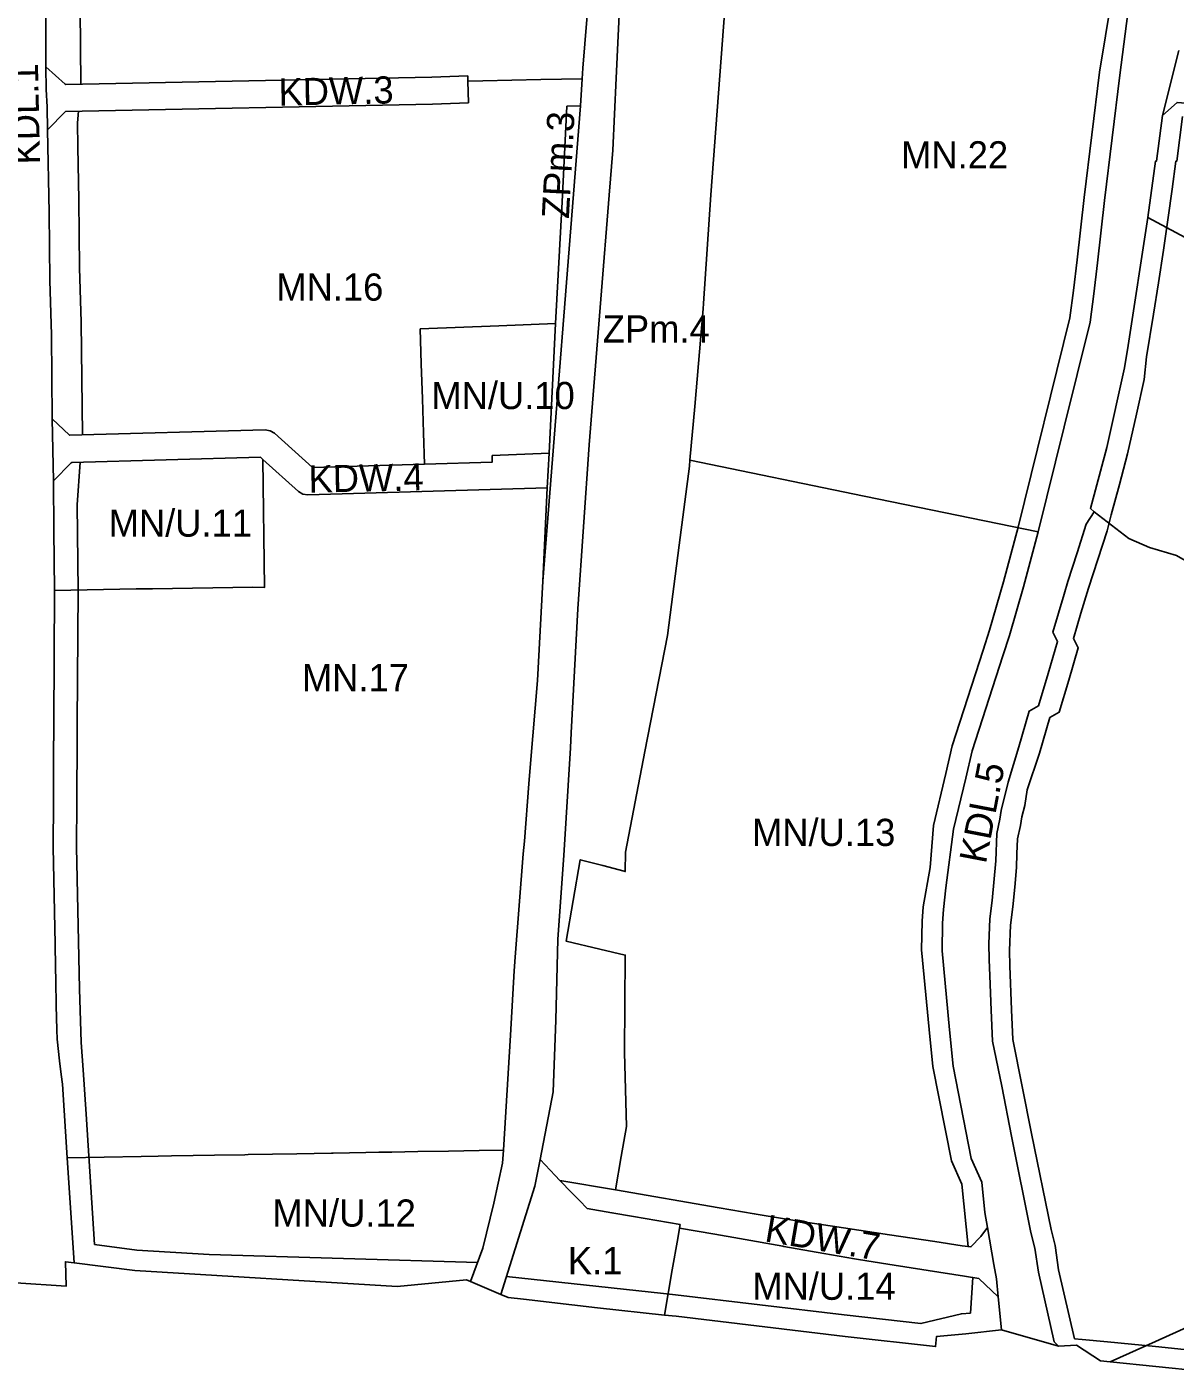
# Model space of a CAD drawing. Extents: x 7431080 to 7433370, y 5546450 to 5548428.
# Drawn here: x 7431653 to 7431991, y 5546819.9 to 5547216.3 of the extents above; entities that cross this region are included whole.
import ezdxf

# ---------------------------------------------------------------- set-up
doc = ezdxf.new("R2010")
doc.units = 0
for name, color, linetype in [('Linie Rozgraniczajace', 7, 'Continuous'), ('nieprzekraczalna linia zabudowy', 7, 'Continuous'), ('oznaczenia_przeznaczen', 7, 'Continuous')]:
    doc.layers.add(name, color=color, linetype=linetype)

msp = doc.modelspace()

# ---------------------------------------------------------------- linework, layer by layer
at = {"layer": 'Linie Rozgraniczajace'}
for p, q in [((7431987.26, 5547190.2), (7431992.07, 5547209.36)), ((7431899.47, 5547078.11), (7431848.17, 5547088.66)), ((7431899.47, 5547078.11), (7431950.67, 5547067.58)), ((7431855.47, 5546860.82), (7431845.13, 5546862.62))]:
    msp.add_line(p, q, dxfattribs=at)
for points in [[(7431658.97, 5547357.52), (7431659.12, 5547345.2), (7431761.61, 5547282.96), (7431765.2, 5547268.96), (7431784.34, 5547269.17), (7431806.85, 5547248.07), (7431819.14, 5547234.05), (7431816.7, 5547204.08)], [(7431982.69, 5547268.13), (7431981.23, 5547251.74), (7431978.31, 5547229.55), (7431974.71, 5547202.02), (7431970.19, 5547165.15), (7431968.19, 5547146.81), (7431967.04, 5547137.69), (7431965.97, 5547129.38), (7431958.32, 5547098.48), (7431950.67, 5547067.58), (7431946.36, 5547051.38), (7431942.22, 5547037.08), (7431940.3, 5547031.13), (7431931.28, 5547003.09), (7431929.38, 5546995.1), (7431925.81, 5546980.02), (7431923.56, 5546962.78), (7431922.79, 5546956.43), (7431922.55, 5546952.38), (7431922.4, 5546944.22), (7431924.59, 5546921)], [(7431658.63, 5547197.82), (7431658.6, 5547204.53), (7431658.49, 5547233.33)], [(7431807.96, 5546902.76), (7431808.69, 5546923.81), (7431809.32, 5546947.71), (7431811.09, 5546972.31), (7431812.99, 5547003.97), (7431813.23, 5547008.39), (7431815.18, 5547044.96), (7431818.54, 5547093.2), (7431821.95, 5547136.09), (7431824.4, 5547166.73), (7431825.46, 5547180), (7431826.45, 5547201.22), (7431827.63, 5547226.19)], [(7431859.01, 5547227.55), (7431858.87, 5547226.83), (7431854.38, 5547166.78), (7431852.22, 5547134.82)], [(7431782.8, 5547201.87), (7431772.18, 5547201.49), (7431664.42, 5547199.34), (7431664.32, 5547199.46), (7431658.6, 5547204.53)], [(7431816.7, 5547204.08), (7431816.5, 5547201), (7431816, 5547193.05)], [(7431782.8, 5547201.87), (7431782.83, 5547200.31), (7431782.97, 5547193.87)], [(7431782.83, 5547200.31), (7431787.25, 5547200.4), (7431795.71, 5547200.57), (7431804.26, 5547200.75), (7431816.5, 5547201)], [(7431659.09, 5547185.94), (7431658.97, 5547192.76), (7431658.63, 5547197.82)], [(7431782.97, 5547193.87), (7431772.43, 5547193.49), (7431772.4, 5547193.5), (7431772.37, 5547193.5), (7431664.34, 5547191.34), (7431659.09, 5547185.94)], [(7431811.96, 5547192.91), (7431810.58, 5547164.75), (7431808.64, 5547128.91), (7431806.7, 5547090.74), (7431806.18, 5547080.57), (7431804.92, 5547053.09), (7431803.27, 5547023.8), (7431801.27, 5546999.43), (7431800.79, 5546993.42), (7431799.46, 5546976.52), (7431799.14, 5546972.84), (7431796.72, 5546942.37), (7431796.47, 5546938.37), (7431795.33, 5546919.43), (7431793.28, 5546885.58), (7431793.05, 5546881.76), (7431790.42, 5546869.94), (7431787.25, 5546856.75), (7431783.62, 5546846.91)], [(7431816, 5547193.05), (7431804.92, 5547053.09)], [(7431811.96, 5547192.91), (7431816, 5547193.05)], [(7431987.26, 5547190.2), (7431985.48, 5547176.73), (7431985.24, 5547176.76), (7431983.01, 5547160.16), (7431977.16, 5547122.42), (7431976.14, 5547115.9), (7431970.95, 5547092.43), (7431966.08, 5547074.52), (7431967.2, 5547073.49), (7431977.34, 5547065.69)], [(7431987.26, 5547190.2), (7431991.61, 5547194.02), (7431996.84, 5547193.65), (7432006.09, 5547192.99), (7432023.49, 5547191.71), (7432040.89, 5547190.43), (7432050.86, 5547189.69), (7432060.83, 5547188.95), (7432081.02, 5547189.02), (7432086.97, 5547188.95), (7432092.93, 5547188.88), (7432094.88, 5547189.01), (7432102.42, 5547188.78), (7432106.42, 5547188.66), (7432117.96, 5547188.31), (7432128.08, 5547187.88), (7432138.21, 5547187.45), (7432142.09, 5547187.22), (7432149.05, 5547187.07), (7432150.13, 5547186.96), (7432151.99, 5547185.41)], [(7431983.01, 5547160.16), (7431996.75, 5547152.83), (7432010.48, 5547145.51), (7432018.88, 5547140.48), (7432027.28, 5547135.45), (7432036.46, 5547129.95), (7432045.63, 5547124.44), (7432053.23, 5547156.7), (7432060.83, 5547188.95)], [(7431659.52, 5547161.65), (7431659.09, 5547185.94)], [(7431660.26, 5547125.65), (7431659.76, 5547141.65), (7431659.52, 5547161.65)], [(7431834.93, 5547002.96), (7431841.55, 5547037.1), (7431845.01, 5547063.71), (7431848.01, 5547086.91), (7431848.17, 5547088.66), (7431849.64, 5547104.47), (7431852.1, 5547133.24), (7431852.22, 5547134.82)], [(7431768.8, 5547127.4), (7431791.91, 5547128.28), (7431808.64, 5547128.91)], [(7431768.8, 5547127.4), (7431769.11, 5547117.08), (7431769.42, 5547106.76), (7431769.73, 5547096.76), (7431770.01, 5547087.51)], [(7431660.96, 5547068.07), (7431660.8, 5547082.63), (7431660.49, 5547100.85), (7431660.26, 5547125.65)], [(7431806.7, 5547090.74), (7431790, 5547090.06), (7431789.95, 5547088.1), (7431770.01, 5547087.51), (7431737.07, 5547086.54), (7431725.89, 5547096.61), (7431724.6, 5547097.39), (7431723.11, 5547097.64), (7431665.54, 5547096.04), (7431660.49, 5547100.85)], [(7431806.18, 5547080.57), (7431735.71, 5547078.5), (7431734.2, 5547078.74), (7431732.91, 5547079.53), (7431722.45, 5547088.95), (7431721.73, 5547089.6), (7431666.27, 5547088.05), (7431666.06, 5547087.91), (7431660.8, 5547082.63)], [(7431661.15, 5547050.37), (7431685.13, 5547050.79), (7431689.99, 5547050.87), (7431719.54, 5547051.34), (7431722.99, 5547051.23), (7431722.45, 5547088.95)], [(7431936.14, 5546946.28), (7431936.42, 5546953.71), (7431937.15, 5546959.11), (7431938.23, 5546970.71), (7431938.51, 5546978.76), (7431939.39, 5546983.03), (7431939.82, 5546985.55), (7431941.85, 5546993.89), (7431944.96, 5547004.35), (7431948.07, 5547014.81), (7431950.8, 5547016.4), (7431953.6, 5547025.86), (7431956.41, 5547035.32), (7431954.99, 5547038.08), (7431958.32, 5547049.24), (7431959.42, 5547052.95), (7431962.15, 5547061.38), (7431964.87, 5547069.82), (7431967.2, 5547073.49)], [(7431660.96, 5547068.07), (7431661.15, 5547050.37), (7431660.92, 5547011.27)], [(7431977.34, 5547065.69), (7431983.49, 5547062.98), (7431991.41, 5547060.6), (7431998.07, 5547056.82), (7432004.72, 5547053.04), (7432008.92, 5547050.71), (7432013.11, 5547048.39), (7432018.79, 5547045.23), (7432032.74, 5547037.1), (7432041.51, 5547032.05)], [(7431660.82, 5546993.21), (7431660.84, 5546998.09), (7431660.81, 5546998.09), (7431660.83, 5546998.12), (7431660.86, 5547006.09), (7431660.89, 5547006.09), (7431660.92, 5547011.27)], [(7431834.93, 5547002.96), (7431832.06, 5546988.12), (7431829.19, 5546973.28), (7431829.16, 5546967.58), (7431828.87, 5546967.66), (7431822.54, 5546969.32), (7431815.91, 5546971.05), (7431813.83, 5546959.09), (7431811.74, 5546947.13), (7431821.7, 5546944.77), (7431829.13, 5546943.01), (7431828.89, 5546914.35)], [(7431660.79, 5546988.4), (7431660.82, 5546993.21)], [(7431661.79, 5546921.03), (7431661.64, 5546928.12), (7431661.49, 5546935.42), (7431661.42, 5546939.42), (7431661.28, 5546946.22), (7431660.72, 5546974.81), (7431660.79, 5546988.4)], [(7431969.09, 5546823.51), (7431961.94, 5546828.15), (7431956.65, 5546827.8), (7431955.45, 5546829.17), (7431950.78, 5546849.61), (7431949.75, 5546856.68), (7431948.58, 5546861.29), (7431942.85, 5546889.69), (7431939.97, 5546904.39), (7431937.25, 5546917.68), (7431936.86, 5546926.75), (7431936.49, 5546936.86), (7431936.31, 5546941.72), (7431936.14, 5546946.28)], [(7431663.45, 5546905.02), (7431663.12, 5546907.83), (7431662.65, 5546911.81), (7431661.89, 5546918.23), (7431661.79, 5546921.03)], [(7431924.59, 5546921), (7431925.68, 5546910.3), (7431931, 5546883.15)], [(7431828.89, 5546914.35), (7431829.21, 5546903.42), (7431829.52, 5546892.49), (7431827.98, 5546883.67), (7431826.28, 5546873.85)], [(7431664.88, 5546883.29), (7431663.45, 5546905.02)], [(7431807.96, 5546902.76), (7431804.07, 5546882.79), (7431802.54, 5546874.94), (7431792.53, 5546843.09)], [(7431664.88, 5546883.29), (7431686.65, 5546883.67), (7431691.66, 5546883.77), (7431695.61, 5546883.84), (7431701.92, 5546883.95), (7431708.19, 5546884.06), (7431717.19, 5546884.22), (7431718.16, 5546884.24), (7431732.44, 5546884.49), (7431742.63, 5546884.67), (7431743.15, 5546884.68), (7431752.81, 5546884.86), (7431756.61, 5546884.92), (7431760.41, 5546884.99), (7431764.24, 5546885.05), (7431768.06, 5546885.12), (7431777.12, 5546885.29), (7431786.19, 5546885.45), (7431793.28, 5546885.58)], [(7431666.92, 5546852.36), (7431664.88, 5546883.29)], [(7431804.07, 5546882.79), (7431808.55, 5546878.11), (7431809.93, 5546876.67), (7431813.4, 5546873.04), (7431815.65, 5546870.72), (7431817.9, 5546868.4), (7431825.24, 5546867.13), (7431831.6, 5546866.02), (7431845.31, 5546863.64)], [(7431931, 5546883.15), (7431934.09, 5546876.11), (7431935.04, 5546867.18), (7431935.81, 5546862.74), (7431937.69, 5546851.92), (7431938.42, 5546847.68), (7431938.96, 5546842.35), (7431939.95, 5546832.62), (7431929.43, 5546831.45), (7431920.8, 5546830.73), (7431920.52, 5546827.74), (7431893.86, 5546830.7), (7431844.16, 5546836.64), (7431840.69, 5546837.02)], [(7431856.8, 5546868.6), (7431826.28, 5546873.85), (7431809.93, 5546876.67)], [(7431935.81, 5546862.74), (7431933.78, 5546860.18), (7431930.89, 5546857.06), (7431928.34, 5546857.4), (7431920.24, 5546858.64), (7431906.95, 5546860.65), (7431893.39, 5546862.68), (7431880.94, 5546864.54), (7431875.98, 5546865.3), (7431867.12, 5546866.83), (7431856.8, 5546868.6)], [(7431845.31, 5546863.64), (7431845.13, 5546862.62), (7431844.61, 5546859.59), (7431843, 5546850.33), (7431840.69, 5546837.02)], [(7431855.47, 5546860.82), (7431862.75, 5546859.55), (7431875.54, 5546857.32), (7431875.83, 5546857.2), (7431887.62, 5546855.14), (7431896.62, 5546853.58), (7431897.84, 5546853.39), (7431906.41, 5546852.02), (7431918.28, 5546850.16), (7431929, 5546848.43), (7431933.19, 5546847.77), (7431938.96, 5546842.35)], [(7431628.52, 5546847.87), (7431639.16, 5546847.17), (7431649.72, 5546846.47), (7431664.61, 5546845.54), (7431664.34, 5546852.7), (7431666.92, 5546852.36), (7431684.77, 5546850.13)], [(7431684.77, 5546850.13), (7431762.02, 5546845.39), (7431782.45, 5546847.41), (7431783.62, 5546846.91)], [(7431783.62, 5546846.91), (7431792.53, 5546843.09), (7431794.71, 5546842.15), (7431799.22, 5546841.64)], [(7431799.22, 5546841.64), (7431813.38, 5546840.03)], [(7431813.38, 5546840.03), (7431820.94, 5546839.17)], [(7431820.94, 5546839.17), (7431840.69, 5546837.02)], [(7432011.7, 5546841.17), (7431985.27, 5546829.24), (7431971.93, 5546823.22)], [(7431939.95, 5546832.62), (7431956.65, 5546827.8)], [(7432007.05, 5546819.09), (7431998.82, 5546820.5), (7431971.93, 5546823.22), (7431969.09, 5546823.51)]]:
    msp.add_lwpolyline(points, dxfattribs=at)
at = {"layer": 'nieprzekraczalna linia zabudowy'}
for points in [[(7431665.52, 5547341.53), (7431668.21, 5547253.27), (7431668.7, 5547221.52), (7431668.87, 5547199.43)], [(7431930.13, 5546857.16), (7431928.18, 5546875.52), (7431925.16, 5546882.4), (7431919.72, 5546910.16), (7431918.61, 5546921.06), (7431916.4, 5546944.52), (7431916.55, 5546952.98), (7431916.8, 5546957.24), (7431918.92, 5546968.75), (7431919.87, 5546981.19), (7431923.49, 5546996.47), (7431925.42, 5547004.61), (7431934.49, 5547032.8), (7431936.39, 5547038.7), (7431940.51, 5547052.9), (7431944.8, 5547069.02), (7431960.03, 5547130.57), (7431961.07, 5547138.64), (7431962.22, 5547147.72), (7431964.22, 5547166.06), (7431968.74, 5547202.97), (7431974.16, 5547235.72), (7431975.25, 5547252.63), (7431976.69, 5547268.76)], [(7431668.18, 5547191.42), (7431667.89, 5547187.99), (7431668.01, 5547180.93), (7431668.29, 5547165.35), (7431668.53, 5547145.38), (7431669.03, 5547129.37), (7431669.34, 5547096.15)], [(7431993.22, 5547189.9), (7431991.48, 5547176.73), (7431991.24, 5547176.76), (7431990.13, 5547168.46), (7431989.01, 5547160.16), (7431987.57, 5547150.55), (7431986.12, 5547140.94), (7431984.64, 5547131.68), (7431982.63, 5547119.11)], [(7431982.63, 5547119.11), (7431981.88, 5547112.44), (7431979.63, 5547102.27), (7431977.04, 5547090.54), (7431974.6, 5547081.58), (7431972.17, 5547072.63), (7431970.96, 5547067.93), (7431968.23, 5547059.49), (7431965.51, 5547051.06), (7431963.3, 5547043.64), (7431961.08, 5547036.19), (7431962.5, 5547033.42), (7431959.69, 5547023.96), (7431956.89, 5547014.5), (7431955.52, 5547013.71), (7431954.16, 5547012.91), (7431951.05, 5547002.45), (7431947.41, 5546991.65), (7431946.74, 5546987.05), (7431945.91, 5546983.66), (7431945.48, 5546981.14), (7431944.64, 5546977.24), (7431944.46, 5546972.84), (7431944.32, 5546968.82), (7431943.78, 5546963.02), (7431943.24, 5546957.21), (7431942.51, 5546951.82), (7431942.23, 5546944.38)], [(7431668.73, 5547088.12), (7431667.79, 5547075.58), (7431668.06, 5547050.33), (7431667.83, 5547011.2), (7431667.78, 5547002.04), (7431667.77, 5547002.04), (7431667.73, 5546993.14), (7431667.7, 5546988.33), (7431667.63, 5546974.79), (7431668.45, 5546933.1)], [(7431942.23, 5546944.38), (7431942.38, 5546939.85), (7431942.86, 5546926.91), (7431943.23, 5546918.17), (7431948.77, 5546890.47), (7431954.48, 5546862.18), (7431955.68, 5546857.46), (7431956.72, 5546850.34), (7431961.36, 5546830.01)], [(7431668.45, 5546933.1), (7431669.02, 5546917.24), (7431669.55, 5546909.17)], [(7431669.55, 5546909.17), (7431670.41, 5546896.13), (7431672.93, 5546857.8)], [(7431672.93, 5546857.8), (7431685.38, 5546856.13), (7431706.62, 5546854.88), (7431785.75, 5546852.53)], [(7431794.19, 5546848.39), (7431840.41, 5546843.36), (7431843.9, 5546842.97), (7431893.6, 5546837.03), (7431916.2, 5546834.52), (7431928.11, 5546837.38), (7431930.74, 5546837.55)], [(7431930.74, 5546837.55), (7431931.49, 5546848.04)], [(7431961.36, 5546830.01), (7431963.62, 5546829.81), (7431971.12, 5546829.14), (7431985.21, 5546827.73), (7431999.3, 5546826.31), (7432007.44, 5546824.79), (7432021.64, 5546823.84), (7432021.64, 5546823.84), (7432046.14, 5546821.94)]]:
    msp.add_lwpolyline(points, dxfattribs=at)

# ---------------------------------------------------------------- texts
at = {"layer": 'oznaczenia_przeznaczen'}
for s, rotation, p in [('KDL.1', 91.241, (7431656.9, 5547175.84)), ('KDW.3', 1.1603, (7431727.15, 5547193.08)), ('ZPm.3', 86.8909, (7431812.54, 5547159.69)), ('ZPm.3', 86.8909, (7431812.54, 5547159.69)), ('KDW.4', 1.1833, (7431735.98, 5547079.12)), ('KDL.5', 79.098, (7431935.28, 5546969.64)), ('KDW.7', 350.2736, (7431869.91, 5546858.75))]:
    msp.add_text(s, height=8, rotation=rotation, dxfattribs=at).set_placement(p)
for s, p in [('MN.22', (7431910.35, 5547174.61)), ('MN.16', (7431726.42, 5547135.67)), ('ZPm.4', (7431822.51, 5547123.35)), ('ZPm.4', (7431822.51, 5547123.35)), ('MN/U.10', (7431772.07, 5547103.74)), ('MN/U.10', (7431772.07, 5547103.74)), ('MN/U.11', (7431677.07, 5547066.18)), ('MN.17', (7431733.96, 5547020.67)), ('MN/U.13', (7431866.44, 5546975.12)), ('MN/U.12', (7431725.3, 5546863.04)), ('K.1', (7431812.24, 5546849)), ('K.1', (7431812.24, 5546849)), ('K.1', (7431812.24, 5546849)), ('MN/U.14', (7431866.54, 5546841.5))]:
    msp.add_text(s, height=8, dxfattribs=at).set_placement(p)

doc.saveas('drawing.dxf')
